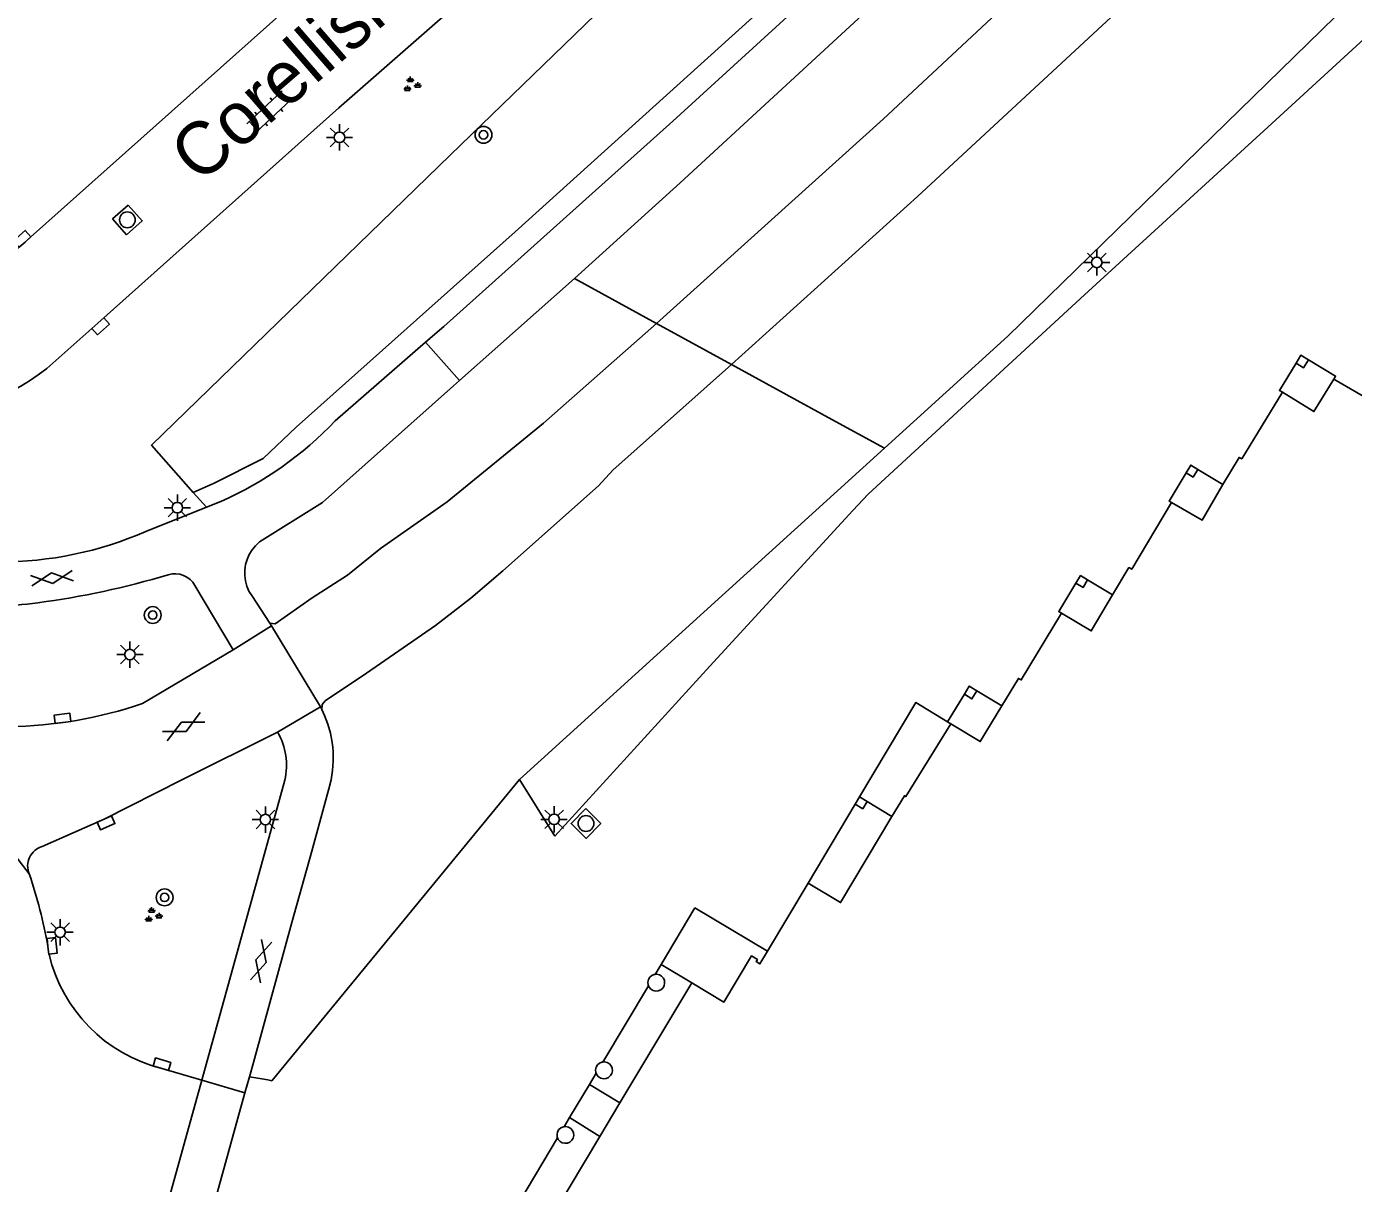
# Model space of a CAD drawing. Extents: x 137999 to 141000, y 397500 to 400501.
# Drawn here: x 138186.2 to 138249.3, y 398678.9 to 398733.9 of the extents above; entities that cross this region are included whole.
import ezdxf

# ---------------------------------------------------------------- set-up
doc = ezdxf.new("R2010")
doc.units = 0
for name, color, linetype in [('gg-afsc-muur', 7, 'Continuous'), ('gg-anno-openbare ruimte label', 7, 'Continuous'), ('gg-bbg-hoofdgebouw', 7, 'Continuous'), ('gg-bbg-luifel en loopbrug', 7, 'Continuous'), ('gg-bbg-onder overbouw', 7, 'Continuous'), ('gg-bbg-pand overbouw', 7, 'Continuous'), ('gg-bbg-pilaar onder overbouw', 7, 'Continuous'), ('gg-bbg-pilaar overkapping', 7, 'Continuous'), ('gg-bbg-pilaar pand', 7, 'Continuous'), ('gg-knt-bronhoudergrens', 7, 'Continuous'), ('gg-knt-verharding', 7, 'Continuous'), ('gg-knt-verharding nz', 7, 'Continuous'), ('gt-grn-groengrens', 7, 'Continuous'), ('gt-grn-weggrens', 7, 'Continuous'), ('gt-symb-boom', 7, 'Continuous'), ('gt-symb-gesloten verharding', 7, 'Continuous'), ('gt-symb-groenvak', 7, 'Continuous'), ('gt-symb-klinker verharding', 7, 'Continuous'), ('gt-symb-kolk', 7, 'Continuous'), ('gt-symb-lichtmast', 7, 'Continuous'), ('gt-symb-rioolschacht', 7, 'Continuous'), ('gx-grn-maaiveld', 7, 'Continuous')]:
    doc.layers.add(name, color=color, linetype=linetype)

# ---------------------------------------------------------------- blocks, each defined once
blk = doc.blocks.new('gt0-KOLK')
at = {"layer": 'gt-symb-kolk'}
blk.add_lwpolyline([(0, 0), (0.375, 0), (0.375, 0.4), (-0.375, 0.4), (-0.375, 0), (0, 0)], dxfattribs=at)
blk = doc.blocks.new('gt0-GESVH1')
at = {"layer": 'gt-symb-gesloten verharding'}
for p, q in [((-0.992, -0.261), (0.008, 0.239)), ((0.008, -0.261), (-0.992, 0.239)), ((0.008, 0.239), (1.008, -0.261)), ((1.008, 0.239), (0.008, -0.261))]:
    blk.add_line(p, q, dxfattribs=at)
blk = doc.blocks.new('gt0-RS')
at = {"layer": 'gt-symb-rioolschacht'}
blk.add_lwpolyline([(-0.5, -0.5), (0.5, -0.5), (0.5, 0.5), (-0.5, 0.5)], close=True, dxfattribs=at)
blk.add_circle((0, 0), 0.375, dxfattribs=at)
blk = doc.blocks.new('gt0-BOOM')
at = {"layer": 'gt-symb-boom'}
for radius in [0.4, 0.2]:
    blk.add_circle((0, 0), radius, dxfattribs=at)
blk = doc.blocks.new('gt0-LMAST')
at = {"layer": 'gt-symb-lichtmast'}
for p, q in [((-0.182, 0.173), (-0.447, 0.438)), ((-0.005, 0.246), (-0.005, 0.621)), ((0.172, 0.173), (0.437, 0.438)), ((-0.255, -0.004), (-0.63, -0.004)), ((-0.182, -0.181), (-0.447, -0.446)), ((-0.005, -0.254), (-0.005, -0.629)), ((0.437, -0.446), (0.172, -0.181)), ((0.245, -0.004), (0.62, -0.004))]:
    blk.add_line(p, q, dxfattribs=at)
blk.add_circle((-0.005, -0.004), 0.25, dxfattribs=at)
blk = doc.blocks.new('gt0-KL1')
at = {"layer": 'gt-symb-klinker verharding'}
for p, q in [((-1.15, 0.3), (1.15, 0.3)), ((-1, -0.3), (-1, 0.3)), ((-0.5, 0.3), (-0.5, 0.45)), ((0, -0.3), (0, 0.3)), ((0.5, 0.3), (0.5, 0.45)), ((1, -0.3), (1, 0.3)), ((-1.15, -0.3), (1.15, -0.3)), ((-0.5, -0.45), (-0.5, -0.3)), ((0.5, -0.45), (0.5, -0.3))]:
    blk.add_line(p, q, dxfattribs=at)
blk = doc.blocks.new('gt0-GRVAK')
at = {"layer": 'gt-symb-groenvak'}
for p, q in [((-0.11, 0.189), (-0.228, 0.24)), ((-0.182, 0.153), (0.088, 0.153)), ((-0.091, 0.211), (-0.156, 0.322)), ((-0.047, 0.214), (-0.047, 0.393)), ((-0.004, 0.211), (0.061, 0.322)), ((0.015, 0.189), (0.133, 0.24)), ((0.262, -0.052), (0.197, 0.059)), ((0.305, -0.049), (0.305, 0.13)), ((0.349, -0.052), (0.414, 0.059)), ((-0.245, -0.228), (-0.363, -0.177)), ((-0.318, -0.264), (-0.047, -0.264)), ((-0.226, -0.206), (-0.291, -0.095)), ((-0.183, -0.203), (-0.183, -0.024)), ((-0.139, -0.206), (-0.074, -0.095)), ((-0.12, -0.228), (-0.002, -0.177)), ((0.243, -0.074), (0.125, -0.023)), ((0.17, -0.11), (0.441, -0.11)), ((0.368, -0.074), (0.486, -0.023))]:
    blk.add_line(p, q, dxfattribs=at)

msp = doc.modelspace()

# ---------------------------------------------------------------- linework, layer by layer
at = {"layer": 'gg-afsc-muur'}
for p, q in [((138217.96, 398692.017), (138216.352, 398689.328)), ((138212.941, 398683.622), (138211.998, 398682.043))]:
    msp.add_line(p, q, dxfattribs=at)
msp.add_lwpolyline([(138225.783, 398697.297), (138228.468, 398701.793), (138229.967, 398700.867)], dxfattribs=at)
at = {"layer": 'gg-bbg-hoofdgebouw'}
for p, q in [((138221.409, 398689.955), (138223.335, 398693.194)), ((138213.434, 398681.147), (138214.391, 398682.743))]:
    msp.add_line(p, q, dxfattribs=at)
for points in [[(138248.345, 398717.169), (138247.395, 398715.621), (138245.899, 398716.539)], [(138257.473, 398711.705), (138255.799, 398712.712), (138255.882, 398712.852), (138250.112, 398716.303), (138250.038, 398716.18), (138248.345, 398717.169)], [(138245.899, 398716.539), (138243.966, 398713.373), (138243.838, 398713.445), (138243.068, 398712.15)], [(138243.068, 398712.15), (138242.079, 398710.45), (138240.627, 398711.294)], [(138240.627, 398711.294), (138238.731, 398708.123), (138238.597, 398708.201), (138237.825, 398706.904)], [(138237.825, 398706.904), (138236.807, 398705.193), (138235.387, 398706.037)], [(138235.387, 398706.037), (138233.479, 398702.858), (138233.34, 398702.931), (138232.553, 398701.628)], [(138232.553, 398701.628), (138231.53, 398699.926), (138230.128, 398700.768)], [(138227.315, 398696.365), (138227.919, 398697.352), (138227.989, 398697.309), (138230.128, 398700.768)], [(138227.315, 398696.365), (138224.886, 398692.269), (138223.335, 398693.194)], [(138221.409, 398689.955), (138221.049, 398689.356), (138220.87, 398689.465), (138220.927, 398689.559), (138220.643, 398689.732), (138219.332, 398687.538), (138217.809, 398688.447)]]:
    msp.add_lwpolyline(points, dxfattribs=at)
at = {"layer": 'gg-bbg-luifel en loopbrug'}
for p, q in [((138243.068, 398712.15), (138241.876, 398712.873)), ((138237.825, 398706.904), (138236.635, 398707.618)), ((138230.775, 398702.176), (138229.967, 398700.867)), ((138232.553, 398701.628), (138231.368, 398702.344)), ((138229.967, 398700.867), (138230.128, 398700.768)), ((138223.335, 398693.194), (138225.577, 398696.951)), ((138225.577, 398696.951), (138225.783, 398697.297)), ((138226.148, 398697.075), (138225.783, 398697.297)), ((138227.315, 398696.365), (138226.148, 398697.075))]:
    msp.add_line(p, q, dxfattribs=at)
for points in [[(138247.136, 398718.083), (138246.773, 398718.3), (138246.546, 398717.924)], [(138246.546, 398717.924), (138245.76, 398716.623), (138245.899, 398716.539)], [(138247.136, 398718.083), (138248.428, 398717.31), (138248.345, 398717.169)], [(138241.321, 398712.705), (138240.51, 398711.364), (138240.627, 398711.294)], [(138241.321, 398712.705), (138241.545, 398713.077), (138241.876, 398712.873)], [(138236.076, 398707.457), (138236.296, 398707.822), (138236.635, 398707.618)], [(138236.076, 398707.457), (138235.263, 398706.112), (138235.387, 398706.037)], [(138230.775, 398702.176), (138231.004, 398702.564), (138231.368, 398702.344)]]:
    msp.add_lwpolyline(points, dxfattribs=at)
at = {"layer": 'gg-bbg-onder overbouw'}
for p, q in [((138214.391, 398682.743), (138217.809, 398688.447)), ((138210.029, 398675.465), (138213.434, 398681.147))]:
    msp.add_line(p, q, dxfattribs=at)
at = {"layer": 'gg-bbg-pand overbouw'}
for p, q in [((138216.067, 398688.851), (138216.352, 398689.328)), ((138216.352, 398689.328), (138217.809, 398688.447)), ((138213.577, 398684.686), (138215.747, 398688.317)), ((138212.941, 398683.622), (138213.26, 398684.156)), ((138212.941, 398683.622), (138214.391, 398682.743)), ((138211.74, 398681.612), (138211.998, 398682.043)), ((138211.998, 398682.043), (138213.434, 398681.147)), ((138209.24, 398677.429), (138211.425, 398681.084))]:
    msp.add_line(p, q, dxfattribs=at)
at = {"layer": 'gg-bbg-pilaar onder overbouw'}
for points in [[(138216.067, 398688.851), (138216.142, 398688.858), (138216.264, 398688.831), (138216.372, 398688.767), (138216.454, 398688.673), (138216.504, 398688.558), (138216.516, 398688.433), (138216.488, 398688.311), (138216.424, 398688.204), (138216.33, 398688.121), (138216.215, 398688.072), (138216.091, 398688.06), (138215.969, 398688.087), (138215.861, 398688.151), (138215.778, 398688.245), (138215.747, 398688.317)], [(138213.577, 398684.686), (138213.657, 398684.693), (138213.779, 398684.666), (138213.887, 398684.602), (138213.969, 398684.508), (138214.019, 398684.393), (138214.03, 398684.269), (138214.003, 398684.146), (138213.939, 398684.039), (138213.845, 398683.956), (138213.73, 398683.907), (138213.605, 398683.895), (138213.483, 398683.923), (138213.376, 398683.986), (138213.293, 398684.08), (138213.26, 398684.156)], [(138211.74, 398681.612), (138211.822, 398681.619), (138211.944, 398681.592), (138212.052, 398681.528), (138212.135, 398681.434), (138212.184, 398681.319), (138212.196, 398681.194), (138212.168, 398681.072), (138212.104, 398680.965), (138212.01, 398680.882), (138211.895, 398680.832), (138211.771, 398680.821), (138211.649, 398680.848), (138211.541, 398680.912), (138211.458, 398681.006), (138211.425, 398681.084)]]:
    msp.add_lwpolyline(points, dxfattribs=at)
at = {"layer": 'gg-bbg-pilaar overkapping'}
for points in [[(138247.136, 398718.083), (138246.909, 398717.705), (138246.546, 398717.924)], [(138241.876, 398712.873), (138241.652, 398712.505), (138241.321, 398712.705)], [(138236.635, 398707.618), (138236.416, 398707.253), (138236.076, 398707.457)], [(138230.775, 398702.176), (138231.135, 398701.959), (138231.368, 398702.344)], [(138225.577, 398696.951), (138225.938, 398696.731), (138226.148, 398697.075)]]:
    msp.add_lwpolyline(points, dxfattribs=at)
at = {"layer": 'gg-bbg-pilaar pand'}
for points in [[(138215.747, 398688.317), (138215.729, 398688.36), (138215.717, 398688.485), (138215.745, 398688.607), (138215.809, 398688.715), (138215.903, 398688.797), (138216.017, 398688.847), (138216.067, 398688.851)], [(138213.26, 398684.156), (138213.243, 398684.195), (138213.232, 398684.32), (138213.259, 398684.442), (138213.323, 398684.55), (138213.417, 398684.632), (138213.532, 398684.682), (138213.577, 398684.686)], [(138211.425, 398681.084), (138211.409, 398681.121), (138211.397, 398681.246), (138211.425, 398681.368), (138211.489, 398681.476), (138211.583, 398681.558), (138211.698, 398681.608), (138211.74, 398681.612)]]:
    msp.add_lwpolyline(points, dxfattribs=at)
at = {"layer": 'gg-knt-bronhoudergrens'}
msp.add_line((138194.497, 398683.82), (138196.553, 398683.216), dxfattribs=at)
msp.add_lwpolyline([(138178.867, 398701.608), (138183.382, 398697.392), (138186.297, 398693.634)], dxfattribs=at)
at = {"layer": 'gg-knt-verharding'}
for p, q in [((138200.091, 398736.162), (138183.801, 398721.645)), ((138200.85, 398715.189), (138205.142, 398718.915)), ((138194.72, 398711.073), (138195.411, 398711.35)), ((138191.839, 398709.92), (138194.72, 398711.073)), ((138194.177, 398707.343), (138195.988, 398704.284)), ((138191.681, 398701.741), (138195.988, 398704.284)), ((138198.445, 398698.09), (138194.497, 398683.82)), ((138209.613, 398698.128), (138197.832, 398683.8)), ((138211.297, 398695.433), (138209.613, 398698.128)), ((138217.96, 398692.017), (138221.409, 398689.955)), ((138187.234, 398689.794), (138187.186, 398690.191)), ((138194.497, 398683.82), (138192.553, 398684.391)), ((138196.553, 398683.216), (138196.767, 398683.987)), ((138194.495, 398675.816), (138196.553, 398683.216))]:
    msp.add_line(p, q, dxfattribs=at)
for points in [[(138187.128, 398717.671), (138189.559, 398719.824), (138201.026, 398730.074), (138209.014, 398737.073), (138218.234, 398745.115), (138227.166, 398753.464), (138238.85, 398764.593), (138246.306, 398771.633), (138264.773, 398789.177), (138275.775, 398799.737)], [(138205.142, 398718.915), (138206.011, 398719.67), (138216.911, 398729.43), (138228.151, 398739.7), (138239.11, 398750), (138259.024, 398769.152)], [(138211.297, 398695.433), (138218.661, 398703.521), (138225.461, 398710.92), (138226.192, 398711.692), (138236.488, 398721.176), (138245.203, 398729.151), (138252.652, 398735.993), (138254.509, 398734.779)], [(138198.11, 398700.377), (138193.55, 398698.11), (138189.865, 398696.244), (138186.912, 398694.931)]]:
    msp.add_lwpolyline(points, dxfattribs=at)
for centre, radius, start, end in [((138180.638, 398725.973), 10.538, 223.96857, 308.01701), ((138188.529, 398726.873), 16.981, 293.91073, 316.52032), ((138184.893, 398725.83), 17.36, 269.8932, 293.58436), ((138181.476, 398746.063), 39.876, 277.52872, 286.64437), ((138193.227, 398706.83), 1.08, 28.38746, 107.74736), ((138184.552, 398721.609), 15.23, 262.75956, 278.11345), ((138185.112, 398720.804), 20.163, 270.58229, 289.01327), ((138195.423, 398698.815), 3.108, 346.50198, 30.16487), ((138187.175, 398694.012), 0.956, 105.96091, 203.30117), ((138162.462, 398685.644), 25.138, 10.42208, 18.5336), ((138194.389, 398691.518), 7.359, 193.54586, 255.55641)]:
    msp.add_arc(centre, radius, start, end, dxfattribs=at)
at = {"layer": 'gg-knt-verharding nz'}
for p, q in [((138195.988, 398704.284), (138197.823, 398705.438)), ((138198.11, 398700.377), (138200.146, 398701.573)), ((138194.497, 398683.82), (138192.491, 398676.6))]:
    msp.add_line(p, q, dxfattribs=at)
at = {"layer": 'gt-grn-groengrens'}
msp.add_line((138194.72, 398711.073), (138194.097, 398711.779), dxfattribs=at)
for points in [[(138339.604, 398847.9), (138315.935, 398825.336), (138286.831, 398797.302), (138267.715, 398779.045), (138227.886, 398740.882), (138209.411, 398724.164), (138198.987, 398714.875), (138197.423, 398713.387), (138195.089, 398712.219), (138194.097, 398711.779)], [(138324.502, 398844.225), (138300.048, 398819.986), (138282.213, 398801.273), (138206.309, 398727.814), (138192.113, 398714.027), (138194.097, 398711.779)]]:
    msp.add_lwpolyline(points, dxfattribs=at)
at = {"layer": 'gt-grn-weggrens'}
for p, q in [((138206.759, 398717.096), (138205.142, 398718.915)), ((138200.146, 398701.573), (138197.823, 398705.438))]:
    msp.add_line(p, q, dxfattribs=at)
at = {"layer": 'gx-grn-maaiveld'}
for p, q in [((138212.232, 398721.951), (138206.759, 398717.096)), ((138212.232, 398721.951), (138216.134, 398719.813)), ((138216.134, 398719.813), (138219.702, 398717.858)), ((138206.474, 398716.843), (138206.759, 398717.096)), ((138206.474, 398716.843), (138200.241, 398711.301)), ((138209.613, 398698.128), (138226.968, 398713.877)), ((138197.246, 398709.419), (138200.241, 398711.301)), ((138196.878, 398706.867), (138197.74, 398705.563)), ((138197.74, 398705.563), (138197.823, 398705.438)), ((138200.146, 398701.573), (138200.206, 398701.447))]:
    msp.add_line(p, q, dxfattribs=at)
for points in [[(138499.407, 398982.656), (138489.916, 398973.847), (138478.635, 398963.661), (138469.403, 398955.249), (138460.33, 398947.221), (138453.633, 398941.068), (138444.667, 398932.821), (138432.975, 398921.772), (138417.262, 398906.589), (138399.636, 398889.594), (138385.045, 398875.638), (138367.167, 398858.322), (138349.331, 398841.156), (138333.867, 398826.239), (138316.875, 398810.072), (138304.822, 398798.46), (138292.221, 398786.299), (138279.233, 398773.798), (138267.431, 398762.44), (138257.964, 398753.347), (138247.335, 398743.355), (138238.393, 398734.962), (138228.544, 398725.848), (138219.702, 398717.858)], [(138331.363, 398835.183), (138326.089, 398830.177), (138318.671, 398823.068), (138300.208, 398805.36), (138285.722, 398791.488), (138272.634, 398778.835), (138261.358, 398768.061), (138249.15, 398756.407), (138237.381, 398745.259), (138226.138, 398734.677), (138217.259, 398726.497), (138212.232, 398721.951)], [(138216.134, 398719.813), (138226.907, 398729.529), (138241.453, 398743.105), (138254.326, 398755.531), (138259.875, 398760.841)], [(138226.968, 398713.877), (138232.837, 398719.204), (138256.19, 398741.997)], [(138216.134, 398719.813), (138210.756, 398715.063), (138206.18, 398711.328), (138202.994, 398709.107), (138201.437, 398707.846), (138199.755, 398706.76), (138197.987, 398705.52), (138197.74, 398705.563)], [(138219.702, 398717.858), (138214.052, 398712.839), (138213.377, 398712.092), (138208.816, 398708.051), (138207.297, 398706.747), (138205.623, 398705.45), (138202.334, 398703.173), (138200.366, 398701.864), (138200.232, 398701.691), (138200.206, 398701.447)], [(138219.702, 398717.858), (138224.464, 398715.249), (138226.968, 398713.877)], [(138196.878, 398706.867), (138196.746, 398707.088), (138196.644, 398707.325), (138196.576, 398707.574), (138196.543, 398707.83), (138196.545, 398708.087), (138196.559, 398708.217), (138196.582, 398708.343), (138196.653, 398708.59), (138196.757, 398708.826), (138196.892, 398709.045), (138197.056, 398709.244), (138197.246, 398709.419)], [(138200.206, 398701.447), (138200.339, 398701.171), (138200.497, 398700.753), (138200.619, 398700.323), (138200.702, 398699.885), (138200.73, 398699.664), (138200.748, 398699.44), (138200.755, 398698.994), (138200.724, 398698.548), (138200.654, 398698.107), (138200.547, 398697.674)], [(138197.049, 398685.008), (138198.791, 398691.317), (138199.73, 398694.717), (138200.547, 398697.674)], [(138196.767, 398683.987), (138196.827, 398684.206), (138197.049, 398685.008)], [(138197.832, 398683.8), (138197.643, 398683.833), (138197.161, 398683.918), (138196.767, 398683.987)]]:
    msp.add_lwpolyline(points, dxfattribs=at)

# ---------------------------------------------------------------- block references
at = {"layer": 'gt-symb-boom'}
for p in [(138207.9, 398728.783), (138192.167, 398705.945), (138192.733, 398692.516)]:
    msp.add_blockref('gt0-BOOM', p, dxfattribs=at)
at = {"layer": 'gt-symb-gesloten verharding'}
for p, rotation in [((138187.369, 398707.707), 7.004259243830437), ((138193.629, 398700.64), 26.436872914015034), ((138197.307, 398689.482), 74.57402962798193)]:
    msp.add_blockref('gt0-GESVH1', p, dxfattribs=dict(at, rotation=rotation))
at = {"layer": 'gt-symb-groenvak'}
for p in [(138204.467, 398731.16), (138192.163, 398691.66)]:
    msp.add_blockref('gt0-GRVAK', p, dxfattribs=at)
at = {"layer": 'gt-symb-klinker verharding', "rotation": 43.05576962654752}
msp.add_blockref('gt0-KL1', (138197.691, 398729.879), dxfattribs=at)
at = {"layer": 'gt-symb-kolk'}
for p, rotation in [((138186.094, 398723.686), 41.67710007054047), ((138189.559, 398719.824), -138.214331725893), ((138187.903, 398700.835), 7.93555037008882), ((138189.865, 398696.244), -156.04914468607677), ((138187.186, 398690.191), -83.05258934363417), ((138192.553, 398684.391), -16.38630565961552)]:
    msp.add_blockref('gt0-KOLK', p, dxfattribs=dict(at, rotation=rotation))
at = {"layer": 'gt-symb-lichtmast'}
for p in [(138201.056, 398728.666), (138237.074, 398722.719), (138193.345, 398711.055), (138191.086, 398704.069), (138197.531, 398696.221), (138211.265, 398696.232), (138187.767, 398690.862)]:
    msp.add_blockref('gt0-LMAST', p, dxfattribs=at)
at = {"layer": 'gt-symb-rioolschacht'}
for p, rotation in [((138190.963, 398724.74), -138.2887188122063), ((138212.774, 398696.032), -134.5948032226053)]:
    msp.add_blockref('gt0-RS', p, dxfattribs=dict(at, rotation=rotation))

# ---------------------------------------------------------------- texts
at = {"layer": 'gg-anno-openbare ruimte label'}
msp.add_text('Corellisingel', height=2.5, rotation=40.9, dxfattribs=at).set_placement((138194.401, 398726.402))

doc.saveas('drawing.dxf')
